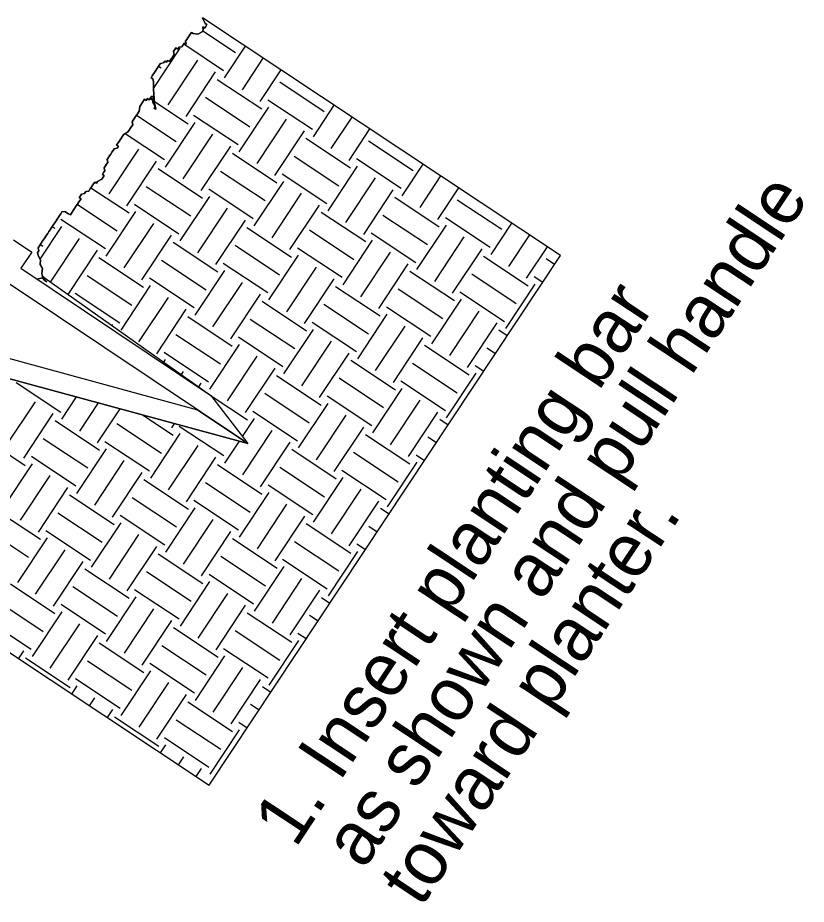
# Model space of a CAD drawing. Extents: x 561231 to 564240, y 590260 to 602519.
# Drawn here: x 563504.6 to 563559.5, y 590746.1 to 590807.7 of the extents above; entities that cross this region are included whole.
import ezdxf

# ---------------------------------------------------------------- set-up
doc = ezdxf.new("R2010")
doc.units = 0
doc.layers.add('Old_Level_1', color=7, linetype='Continuous')

msp = doc.modelspace()

# ---------------------------------------------------------------- linework, layer by layer
at = {"layer": 'Old_Level_1'}
for p, q in [((563542.363, 590791.2), (563517.444, 590807.729)), ((563517.468, 590806.819), (563519.742, 590805.31)), ((563514.037, 590802.814), (563515.887, 590805.602)), ((563516.147, 590805.909), (563518.919, 590804.07)), ((563518.987, 590803.545), (563520.443, 590805.74)), ((563514.399, 590804.356), (563514.57, 590804.243)), ((563515.07, 590801.679), (563517.127, 590804.779)), ((563520.227, 590802.723), (563521.683, 590804.917)), ((563516.31, 590800.856), (563518.367, 590803.956)), ((563521.467, 590801.9), (563522.923, 590804.095)), ((563518.471, 590803.441), (563521.572, 590801.385)), ((563522.821, 590803.268), (563525.921, 590801.211)), ((563513.804, 590802.106), (563514.012, 590801.968)), ((563514.111, 590801.902), (563516.451, 590800.349)), ((563517.649, 590802.201), (563520.749, 590800.144)), ((563521.998, 590802.028), (563525.099, 590799.971)), ((563520.009, 590798.403), (563522.066, 590801.503)), ((563525.166, 590799.447), (563526.622, 590801.641)), ((563512.857, 590800.948), (563515.629, 590799.109)), ((563516.826, 590800.961), (563519.926, 590798.904)), ((563521.249, 590797.58), (563523.306, 590800.681)), ((563526.406, 590798.624), (563527.862, 590800.819)), ((563514.874, 590797.345), (563516.93, 590800.445)), ((563512.081, 590799.677), (563514.806, 590797.869)), ((563516.114, 590796.522), (563518.17, 590799.623)), ((563522.489, 590796.758), (563524.546, 590799.858)), ((563527.646, 590797.802), (563529.102, 590799.996)), ((563517.354, 590795.7), (563519.411, 590798.8)), ((563524.65, 590799.342), (563527.75, 590797.286)), ((563529, 590799.169), (563532.1, 590797.112)), ((563510.957, 590795.478), (563513.013, 590798.578)), ((563519.53, 590798.307), (563522.63, 590796.251)), ((563512.197, 590794.656), (563514.254, 590797.756)), ((563523.828, 590798.102), (563526.928, 590796.046)), ((563528.177, 590797.929), (563531.278, 590795.872)), ((563531.345, 590795.348), (563532.801, 590797.543)), ((563514.358, 590797.24), (563517.458, 590795.184)), ((563518.707, 590797.067), (563521.808, 590795.01)), ((563526.188, 590794.304), (563528.245, 590797.405)), ((563521.052, 590793.246), (563523.109, 590796.347)), ((563523.005, 590796.862), (563526.105, 590794.805)), ((563527.428, 590793.482), (563529.485, 590796.582)), ((563532.585, 590794.526), (563534.041, 590796.72)), ((563509.691, 590795.905), (563512.338, 590794.149)), ((563513.535, 590796), (563516.635, 590793.944)), ((563517.885, 590795.827), (563520.985, 590793.77)), ((563528.668, 590792.659), (563530.725, 590795.759)), ((563533.825, 590793.703), (563535.281, 590795.897)), ((563515.896, 590792.202), (563517.952, 590795.303)), ((563522.293, 590792.424), (563524.349, 590795.524)), ((563530.829, 590795.244), (563533.929, 590793.187)), ((563508.743, 590794.747), (563511.516, 590792.908)), ((563512.713, 590794.76), (563515.813, 590792.703)), ((563517.136, 590791.38), (563519.192, 590794.48)), ((563523.533, 590791.601), (563525.589, 590794.701)), ((563535.179, 590795.07), (563538.279, 590793.014)), ((563510.76, 590791.144), (563512.817, 590794.245)), ((563525.709, 590794.208), (563528.81, 590792.152)), ((563530.007, 590794.003), (563533.107, 590791.947)), ((563507.593, 590793.725), (563510.693, 590791.668)), ((563512.001, 590790.322), (563514.057, 590793.422)), ((563518.376, 590790.557), (563520.433, 590793.657)), ((563532.367, 590790.206), (563534.424, 590793.306)), ((563534.356, 590793.83), (563537.456, 590791.773)), ((563537.524, 590791.249), (563538.98, 590793.444)), ((563506.165, 590790.946), (563507.66, 590793.2)), ((563506.995, 590793.195), (563507.166, 590793.082)), ((563520.537, 590793.142), (563523.637, 590791.085)), ((563524.886, 590792.968), (563527.987, 590790.912)), ((563529.184, 590792.763), (563532.284, 590790.707)), ((563538.765, 590790.427), (563540.22, 590792.621)), ((563504.306, 590792.284), (563505.58, 590791.432)), ((563506.886, 590789.342), (563508.901, 590792.378)), ((563513.241, 590789.499), (563515.297, 590792.599)), ((563515.417, 590792.106), (563518.518, 590790.05)), ((563527.232, 590789.147), (563529.288, 590792.248)), ((563533.607, 590789.383), (563535.664, 590792.483)), ((563505.58, 590791.432), (563504.821, 590790.297)), ((563506.173, 590791.955), (563506.343, 590791.842)), ((563508.102, 590788.482), (563510.141, 590791.555)), ((563519.714, 590791.901), (563522.815, 590789.845)), ((563524.064, 590791.728), (563527.164, 590789.671)), ((563528.472, 590788.325), (563530.528, 590791.425)), ((563534.847, 590788.56), (563536.904, 590791.661)), ((563540.004, 590789.604), (563541.46, 590791.799)), ((563510.245, 590791.04), (563513.345, 590788.983)), ((563514.594, 590790.866), (563517.695, 590788.81)), ((563517.914, 590754.344), (563542.363, 590791.2)), ((563522.075, 590788.104), (563524.131, 590791.204)), ((563537.008, 590791.145), (563540.109, 590789.088)), ((563541.358, 590790.971), (563541.95, 590790.579)), ((563504.821, 590790.297), (563518.026, 590781.459)), ((563516.94, 590787.045), (563518.996, 590790.145)), ((563518.892, 590790.661), (563521.992, 590788.605)), ((563523.315, 590787.281), (563525.372, 590790.381)), ((563529.712, 590787.502), (563531.768, 590790.602)), ((563505.99, 590789.564), (563506.443, 590789.656)), ((563506.443, 590789.656), (563518.026, 590781.459)), ((563509.422, 590789.799), (563512.523, 590787.743)), ((563513.772, 590789.626), (563516.872, 590787.57)), ((563524.555, 590786.458), (563526.612, 590789.559)), ((563531.888, 590790.11), (563534.989, 590788.053)), ((563536.185, 590789.905), (563539.286, 590787.848)), ((563540.535, 590789.731), (563541.128, 590789.339)), ((563520.616, 590778.102), (563504.07, 590789.176)), ((563511.783, 590786.002), (563513.839, 590789.102)), ((563518.18, 590786.223), (563520.236, 590789.323)), ((563526.716, 590789.043), (563529.817, 590786.986)), ((563538.546, 590786.107), (563540.602, 590789.207)), ((563508.6, 590788.559), (563511.7, 590786.503)), ((563519.42, 590785.4), (563521.476, 590788.5)), ((563531.066, 590788.869), (563534.166, 590786.813)), ((563535.363, 590788.664), (563538.464, 590786.608)), ((563513.023, 590785.179), (563515.079, 590788.279)), ((563521.596, 590788.008), (563524.697, 590785.951)), ((563525.893, 590787.803), (563528.994, 590785.746)), ((563533.411, 590785.049), (563535.468, 590788.149)), ((563509.925, 590787.192), (563509.944, 590787.221)), ((563514.263, 590784.356), (563516.32, 590787.457)), ((563528.254, 590784.004), (563530.31, 590787.105)), ((563530.243, 590787.629), (563533.344, 590785.573)), ((563534.651, 590784.226), (563536.708, 590787.326)), ((563516.424, 590786.941), (563519.525, 590784.884)), ((563520.774, 590786.768), (563523.874, 590784.711)), ((563525.071, 590786.562), (563528.171, 590784.506)), ((563535.891, 590783.403), (563537.948, 590786.503)), ((563511.14, 590786.332), (563511.184, 590786.399)), ((563523.119, 590782.947), (563525.175, 590786.047)), ((563529.494, 590783.182), (563531.551, 590786.283)), ((563538.067, 590786.011), (563538.66, 590785.618)), ((563515.601, 590785.701), (563518.702, 590783.644)), ((563519.951, 590785.528), (563523.051, 590783.471)), ((563524.359, 590782.124), (563526.415, 590785.224)), ((563530.734, 590782.36), (563532.791, 590785.46)), ((563501.761, 590784.635), (563517.093, 590780.46)), ((563517.962, 590781.902), (563520.018, 590785.003)), ((563532.895, 590784.944), (563535.996, 590782.888)), ((563537.245, 590784.771), (563537.837, 590784.378)), ((563514.779, 590784.461), (563517.879, 590782.404)), ((563519.202, 590781.08), (563521.258, 590784.181)), ((563525.599, 590781.301), (563527.656, 590784.402)), ((563514.765, 590783.767), (563514.883, 590783.945)), ((563520.442, 590780.258), (563522.498, 590783.358)), ((563527.776, 590783.909), (563530.876, 590781.852)), ((563532.073, 590783.704), (563535.173, 590781.647)), ((563536.422, 590783.531), (563537.015, 590783.138)), ((563520.616, 590778.102), (563501.406, 590783.333)), ((563501.406, 590783.333), (563520.616, 590778.102)), ((563520.616, 590778.102), (563501.406, 590783.333)), ((563515.98, 590782.907), (563516.123, 590783.122)), ((563522.603, 590782.842), (563525.704, 590780.786)), ((563534.433, 590779.906), (563536.49, 590783.006)), ((563504.487, 590782.359), (563507.587, 590780.302)), ((563517.196, 590782.047), (563517.364, 590782.3)), ((563526.953, 590782.669), (563530.053, 590780.612)), ((563531.25, 590782.464), (563534.35, 590780.407)), ((563521.781, 590781.602), (563524.881, 590779.545)), ((563529.298, 590778.848), (563531.354, 590781.948)), ((563503.774, 590777.92), (563505.831, 590781.02)), ((563507.67, 590779.8), (563508.696, 590781.348)), ((563508.91, 590778.978), (563510.208, 590780.936)), ((563518.026, 590781.459), (563520.616, 590778.102)), ((563518.026, 590781.459), (563520.616, 590778.102)), ((563518.046, 590781.433), (563520.583, 590779.75)), ((563524.141, 590777.804), (563526.198, 590780.904)), ((563526.13, 590781.429), (563529.231, 590779.372)), ((563530.538, 590778.025), (563532.594, 590781.125)), ((563510.15, 590778.155), (563511.721, 590780.524)), ((563517.093, 590780.46), (563520.616, 590778.102)), ((563520.958, 590780.362), (563524.058, 590778.305)), ((563531.778, 590777.202), (563533.835, 590780.303)), ((563505.014, 590777.097), (563507.071, 590780.198)), ((563507.191, 590779.705), (563510.291, 590777.648)), ((563513.273, 590780.102), (563515.411, 590778.684)), ((563520.233, 590778.597), (563521.062, 590779.846)), ((563525.381, 590776.981), (563527.438, 590780.082)), ((563533.954, 590779.81), (563534.546, 590779.418)), ((563511.488, 590779.5), (563514.589, 590777.443)), ((563515.307, 590779.199), (563515.503, 590779.494)), ((563515.838, 590779.327), (563518.938, 590777.27)), ((563526.621, 590776.159), (563528.678, 590779.259)), ((563502.019, 590778.638), (563505.119, 590776.582)), ((563506.368, 590778.465), (563509.468, 590776.408)), ((563513.848, 590775.702), (563515.905, 590778.802)), ((563520.246, 590775.923), (563522.302, 590779.024)), ((563528.782, 590778.743), (563531.882, 590776.687)), ((563533.132, 590778.57), (563533.724, 590778.177)), ((563510.666, 590778.26), (563513.766, 590776.203)), ((563515.089, 590774.879), (563517.145, 590777.98)), ((563519.006, 590776.746), (563520.014, 590778.266)), ((563521.486, 590775.1), (563523.543, 590778.201)), ((563505.546, 590777.225), (563508.646, 590775.168)), ((563508.713, 590774.644), (563510.77, 590777.744)), ((563523.662, 590777.708), (563526.762, 590775.652)), ((563527.96, 590777.503), (563531.06, 590775.447)), ((563532.309, 590777.33), (563532.901, 590776.937)), ((563503.556, 590773.6), (563505.613, 590776.7)), ((563509.953, 590773.821), (563512.01, 590776.922)), ((563516.329, 590774.057), (563518.385, 590777.157)), ((563518.49, 590776.641), (563521.59, 590774.585)), ((563530.32, 590773.705), (563532.377, 590776.806)), ((563511.193, 590772.998), (563513.25, 590776.099)), ((563522.839, 590776.468), (563525.94, 590774.411)), ((563527.137, 590776.263), (563530.237, 590774.207)), ((563504.797, 590772.777), (563506.853, 590775.878)), ((563513.37, 590775.606), (563516.47, 590773.55)), ((563517.667, 590775.401), (563520.767, 590773.345)), ((563525.184, 590772.647), (563527.241, 590775.747)), ((563506.037, 590771.955), (563508.093, 590775.055)), ((563522.017, 590775.228), (563525.117, 590773.171)), ((563526.425, 590771.824), (563528.481, 590774.925)), ((563508.198, 590774.539), (563511.298, 590772.483)), ((563512.547, 590774.366), (563515.648, 590772.309)), ((563516.845, 590774.161), (563519.945, 590772.104)), ((563520.027, 590771.603), (563522.084, 590774.704)), ((563503.078, 590773.504), (563506.178, 590771.448)), ((563514.892, 590770.545), (563516.949, 590773.645)), ((563521.268, 590770.781), (563523.324, 590773.881)), ((563527.665, 590771.002), (563529.721, 590774.102)), ((563529.841, 590773.609), (563530.433, 590773.216)), ((563507.375, 590773.299), (563510.475, 590771.243)), ((563511.724, 590773.126), (563514.825, 590771.069)), ((563522.508, 590769.958), (563524.564, 590773.058)), ((563502.255, 590772.264), (563505.355, 590770.207)), ((563509.736, 590769.501), (563511.792, 590772.602)), ((563516.132, 590769.722), (563518.189, 590772.823)), ((563524.669, 590772.543), (563527.769, 590770.486)), ((563529.018, 590772.369), (563529.611, 590771.976)), ((563506.552, 590772.059), (563509.653, 590770.002)), ((563510.976, 590768.679), (563513.032, 590771.779)), ((563517.373, 590768.9), (563519.429, 590772)), ((563504.6, 590768.443), (563506.657, 590771.544)), ((563519.549, 590771.507), (563522.649, 590769.451)), ((563523.846, 590771.302), (563526.946, 590769.246)), ((563528.196, 590771.129), (563528.788, 590770.736)), ((563492.996, 590770.873), (563517.914, 590754.344)), ((563505.84, 590767.62), (563507.897, 590770.721)), ((563512.216, 590767.856), (563514.272, 590770.956)), ((563514.377, 590770.441), (563517.477, 590768.384)), ((563526.207, 590767.505), (563528.263, 590770.605)), ((563507.08, 590766.798), (563509.137, 590769.898)), ((563518.726, 590770.267), (563521.827, 590768.211)), ((563523.024, 590770.062), (563526.124, 590768.006)), ((563509.257, 590769.405), (563512.357, 590767.349)), ((563513.554, 590769.2), (563516.654, 590767.144)), ((563521.072, 590766.446), (563523.128, 590769.547)), ((563517.904, 590769.027), (563521.004, 590766.97)), ((563522.311, 590765.624), (563524.368, 590768.724)), ((563504.084, 590768.339), (563507.185, 590766.282)), ((563508.434, 590768.165), (563511.534, 590766.109)), ((563512.731, 590767.96), (563515.832, 590765.904)), ((563515.915, 590765.403), (563517.971, 590768.503)), ((563510.779, 590764.344), (563512.836, 590767.445)), ((563517.155, 590764.58), (563519.211, 590767.68)), ((563523.552, 590764.801), (563525.608, 590767.901)), ((563525.728, 590767.409), (563526.32, 590767.016)), ((563503.262, 590767.098), (563506.362, 590765.042)), ((563507.611, 590766.925), (563510.712, 590764.868)), ((563518.395, 590763.757), (563520.452, 590766.858)), ((563505.622, 590763.301), (563507.679, 590766.401)), ((563512.02, 590763.522), (563514.076, 590766.622)), ((563520.556, 590766.342), (563523.656, 590764.285)), ((563524.905, 590766.168), (563525.497, 590765.776)), ((563502.439, 590765.858), (563505.539, 590763.802)), ((563506.862, 590762.478), (563508.919, 590765.578)), ((563513.259, 590762.699), (563515.316, 590765.799)), ((563515.436, 590765.307), (563518.536, 590763.25)), ((563519.733, 590765.102), (563522.833, 590763.045)), ((563524.083, 590764.928), (563524.675, 590764.536)), ((563508.102, 590761.655), (563510.159, 590764.756)), ((563522.093, 590761.304), (563524.15, 590764.404)), ((563504.654, 590763.14), (563505.024, 590763.697)), ((563510.263, 590764.24), (563513.364, 590762.183)), ((563514.613, 590764.066), (563517.713, 590762.01)), ((563518.911, 590763.861), (563522.011, 590761.805)), ((563505.143, 590763.205), (563508.244, 590761.148)), ((563516.958, 590760.245), (563519.015, 590763.346)), ((563509.441, 590763), (563512.541, 590760.943)), ((563513.79, 590762.826), (563516.891, 590760.77)), ((563518.199, 590759.423), (563520.255, 590762.523)), ((563511.801, 590759.202), (563513.858, 590762.302)), ((563508.353, 590760.686), (563508.723, 590761.244)), ((563508.618, 590761.759), (563511.718, 590759.703)), ((563513.041, 590758.379), (563515.098, 590761.48)), ((563519.439, 590758.6), (563521.495, 590761.7)), ((563521.615, 590761.208), (563522.207, 590760.815)), ((563514.281, 590757.556), (563516.338, 590760.657)), ((563509.593, 590759.864), (563509.963, 590760.421)), ((563516.442, 590760.141), (563519.543, 590758.084)), ((563520.792, 590759.968), (563521.384, 590759.575)), ((563510.833, 590759.041), (563511.203, 590759.598)), ((563511.323, 590759.106), (563514.423, 590757.049)), ((563515.62, 590758.901), (563518.721, 590756.844)), ((563519.969, 590758.727), (563520.562, 590758.335)), ((563517.98, 590755.103), (563520.037, 590758.203)), ((563514.797, 590757.661), (563517.898, 590755.604)), ((563514.532, 590756.588), (563514.902, 590757.145)), ((563515.772, 590755.765), (563516.142, 590756.322)), ((563517.012, 590754.942), (563517.382, 590755.5))]:
    msp.add_line(p, q, dxfattribs=at)
for points in [[(563513.087, 590801.565), (563513.252, 590801.814), (563513.335, 590801.939), (563513.417, 590802.063), (563513.542, 590801.981), (563513.624, 590802.106), (563513.749, 590802.023), (563513.624, 590802.106), (563513.749, 590802.023), (563513.831, 590802.147), (563513.956, 590802.064), (563513.831, 590802.147), (563513.915, 590802.272), (563514.039, 590802.189), (563513.998, 590801.858), (563514.164, 590801.568), (563514.082, 590801.443), (563514.207, 590801.361), (563514.123, 590801.775), (563514.037, 590802.728), (563514.036, 590803.267), (563513.994, 590803.474), (563513.869, 590803.557), (563513.952, 590803.681), (563514.117, 590803.931), (563514.199, 590804.055), (563514.282, 590804.18), (563514.365, 590804.304), (563514.447, 590804.429), (563514.53, 590804.553), (563514.737, 590804.595), (563514.82, 590804.719), (563514.944, 590804.637), (563515.027, 590804.761), (563515.152, 590804.679), (563515.235, 590804.803), (563515.317, 590804.927), (563515.482, 590805.176), (563515.44, 590805.384), (563515.523, 590805.508), (563515.605, 590805.633), (563515.73, 590805.55), (563515.813, 590805.674), (563516.02, 590805.716), (563516.102, 590805.841), (563516.185, 590805.966), (563516.309, 590805.883), (563516.267, 590806.09), (563516.35, 590806.215), (563516.432, 590806.339), (563516.516, 590806.464), (563516.598, 590806.588), (563516.681, 590806.713), (563516.805, 590806.63), (563517.137, 590806.589), (563517.427, 590806.756), (563517.509, 590806.88), (563517.467, 590807.087), (563517.592, 590807.004), (563517.675, 590807.129), (563517.757, 590807.253), (563517.632, 590807.336), (563517.444, 590807.729), (563517.444, 590807.729)], [(563517.444, 590807.729), (563517.444, 590807.729), (563517.632, 590807.336), (563517.757, 590807.253), (563517.675, 590807.129), (563517.592, 590807.004), (563517.467, 590807.087), (563517.509, 590806.88), (563517.427, 590806.756), (563517.137, 590806.589), (563516.805, 590806.63), (563516.681, 590806.713), (563516.598, 590806.588), (563516.516, 590806.464), (563516.432, 590806.339), (563516.35, 590806.215), (563516.267, 590806.09), (563516.309, 590805.883), (563516.185, 590805.966), (563516.102, 590805.841), (563516.02, 590805.716), (563515.813, 590805.674), (563515.73, 590805.55), (563515.605, 590805.633), (563515.523, 590805.508), (563515.44, 590805.384), (563515.482, 590805.176), (563515.317, 590804.927), (563515.235, 590804.803), (563515.152, 590804.679), (563515.027, 590804.761), (563514.944, 590804.637), (563514.82, 590804.719), (563514.737, 590804.595), (563514.53, 590804.553), (563514.447, 590804.429), (563514.365, 590804.304), (563514.282, 590804.18), (563514.199, 590804.055), (563514.117, 590803.931), (563513.952, 590803.681), (563513.869, 590803.557), (563513.994, 590803.474), (563514.036, 590803.267), (563514.037, 590802.728), (563514.123, 590801.775), (563514.207, 590801.361), (563514.082, 590801.443), (563514.164, 590801.568), (563513.998, 590801.858), (563514.039, 590802.189), (563513.915, 590802.272), (563513.831, 590802.147), (563513.956, 590802.064), (563513.831, 590802.147), (563513.749, 590802.023), (563513.624, 590802.106), (563513.749, 590802.023), (563513.624, 590802.106), (563513.542, 590801.981), (563513.417, 590802.063), (563513.335, 590801.939), (563513.252, 590801.814), (563513.087, 590801.565)], [(563505.99, 590789.564), (563506.028, 590789.572), (563506.443, 590789.656), (563506.36, 590789.532), (563506.485, 590789.449), (563506.609, 590789.367), (563506.485, 590789.449), (563506.443, 590789.656), (563506.318, 590789.739), (563506.276, 590789.946), (563506.316, 590790.278), (563506.15, 590790.567), (563506.191, 590790.899), (563506.024, 590791.189), (563505.982, 590791.396), (563506.065, 590791.52), (563506.023, 590791.728), (563506.105, 590791.852), (563506.188, 590791.977), (563506.353, 590792.226), (563506.436, 590792.351), (563506.601, 590792.6), (563506.684, 590792.724), (563506.766, 590792.849), (563506.849, 590792.973), (563506.931, 590793.097), (563507.013, 590793.222), (563507.261, 590793.596), (563507.344, 590793.72), (563507.427, 590793.845), (563507.509, 590793.969), (563507.592, 590794.094), (563507.675, 590794.218), (563507.882, 590794.26), (563508.131, 590794.094), (563508.256, 590794.012), (563508.339, 590794.137), (563508.503, 590794.386), (563508.669, 590794.634), (563508.751, 590794.759), (563508.834, 590794.884), (563508.916, 590795.008), (563508.999, 590795.133), (563508.875, 590795.215), (563508.957, 590795.339), (563509.04, 590795.464), (563509.247, 590795.506), (563509.33, 590795.631), (563509.536, 590795.673), (563509.619, 590795.797), (563509.702, 590795.921), (563509.784, 590796.047), (563509.867, 590796.171), (563509.95, 590796.295), (563510.074, 590796.212), (563510.157, 590796.337), (563510.446, 590796.503), (563510.529, 590796.628), (563510.612, 590796.753), (563510.488, 590796.835), (563510.57, 590796.96), (563510.653, 590797.084), (563510.61, 590797.291), (563510.693, 590797.416), (563510.775, 590797.54), (563510.858, 590797.665), (563510.816, 590797.872), (563510.982, 590798.121), (563511.064, 590798.246), (563511.147, 590798.37), (563511.229, 590798.494), (563511.312, 590798.619), (563511.519, 590798.661), (563511.601, 590798.785), (563511.477, 590798.868), (563511.56, 590798.993), (563511.642, 590799.117), (563511.725, 590799.242), (563511.807, 590799.366), (563511.89, 590799.49), (563511.972, 590799.615), (563512.262, 590799.781), (563512.345, 590799.906), (563512.428, 590800.03), (563512.51, 590800.155), (563512.593, 590800.28), (563512.551, 590800.486), (563512.633, 590800.611), (563512.716, 590800.736), (563512.799, 590800.86), (563512.881, 590800.985), (563513.046, 590801.234), (563513.087, 590801.565)], [(563513.087, 590801.565), (563513.046, 590801.234), (563512.881, 590800.985), (563512.799, 590800.86), (563512.716, 590800.736), (563512.633, 590800.611), (563512.551, 590800.486), (563512.593, 590800.28), (563512.51, 590800.155), (563512.428, 590800.03), (563512.345, 590799.906), (563512.262, 590799.781), (563511.972, 590799.615), (563511.89, 590799.49), (563511.807, 590799.366), (563511.725, 590799.242), (563511.642, 590799.117), (563511.56, 590798.993), (563511.477, 590798.868), (563511.601, 590798.785), (563511.519, 590798.661), (563511.312, 590798.619), (563511.229, 590798.494), (563511.147, 590798.37), (563511.064, 590798.246), (563510.982, 590798.121), (563510.816, 590797.872), (563510.858, 590797.665), (563510.775, 590797.54), (563510.693, 590797.416), (563510.61, 590797.291), (563510.653, 590797.084), (563510.57, 590796.96), (563510.488, 590796.835), (563510.612, 590796.753), (563510.529, 590796.628), (563510.446, 590796.503), (563510.157, 590796.337), (563510.074, 590796.212), (563509.95, 590796.295), (563509.867, 590796.171), (563509.784, 590796.047), (563509.702, 590795.921), (563509.619, 590795.797), (563509.536, 590795.673), (563509.33, 590795.631), (563509.247, 590795.506), (563509.04, 590795.464), (563508.957, 590795.339), (563508.875, 590795.215), (563508.999, 590795.133), (563508.916, 590795.008), (563508.834, 590794.884), (563508.751, 590794.759), (563508.669, 590794.634), (563508.503, 590794.386), (563508.339, 590794.137), (563508.256, 590794.012), (563508.131, 590794.094), (563507.882, 590794.26), (563507.675, 590794.218), (563507.592, 590794.094), (563507.509, 590793.969), (563507.427, 590793.845), (563507.344, 590793.72), (563507.261, 590793.596), (563507.013, 590793.222), (563506.931, 590793.097), (563506.849, 590792.973), (563506.766, 590792.849), (563506.684, 590792.724), (563506.601, 590792.6), (563506.436, 590792.351), (563506.353, 590792.226), (563506.188, 590791.977), (563506.105, 590791.852), (563506.023, 590791.728), (563506.065, 590791.52), (563505.982, 590791.396), (563506.024, 590791.189), (563506.191, 590790.899), (563506.15, 590790.567), (563506.316, 590790.278), (563506.276, 590789.946), (563506.318, 590789.739), (563506.443, 590789.656), (563506.485, 590789.449), (563506.609, 590789.367), (563506.485, 590789.449), (563506.36, 590789.532), (563506.443, 590789.656), (563506.028, 590789.572), (563505.99, 590789.564)]]:
    msp.add_lwpolyline(points, dxfattribs=at)

# ---------------------------------------------------------------- texts
for s, p in [(' as shown and pull handle ', (563527.904, 590747.26)), ('1. Insert planting bar ', (563523.918, 590749.904)), (' toward planter.', (563531.891, 590744.615))]:
    msp.add_text(s, height=3.72047, rotation=56.44242, dxfattribs=at).set_placement(p)

doc.saveas('drawing.dxf')
